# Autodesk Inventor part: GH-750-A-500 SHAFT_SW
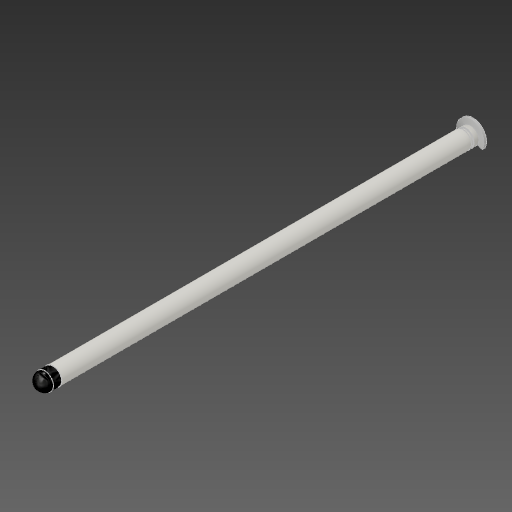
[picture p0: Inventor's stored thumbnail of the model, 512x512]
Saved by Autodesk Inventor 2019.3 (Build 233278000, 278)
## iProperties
Created: 2018-11
Part Number: GH-750-A-500 SHAFT_SW
Material: Generic
Document SubType Name: Modeling
Designer: Justin
Density: 1 g/cm^3
Appearance: Default
Mass: 3.30987 g
Surface Area: 27.5865 cm^2
Volume: 3.30987 cm^3
Author: Justin
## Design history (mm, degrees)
node "Assembly1" dims "d0" = 10
body "Solid1"
node "Part1:1" dims "d0" = 10
node "Part2:1" dims "d0" = 10
body "Solid2"
node "Part3:1" dims "d0" = 10
body "Solid3"
